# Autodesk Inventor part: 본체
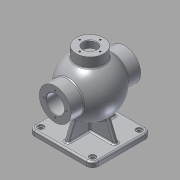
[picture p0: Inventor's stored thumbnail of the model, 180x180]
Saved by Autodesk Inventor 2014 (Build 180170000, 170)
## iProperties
Created: 2015-10
Part Number: 본체
Material: Aluminum 6061
Document SubType Name: Modeling
Designer: youjin19
Density: 2.71 g/cm^3
Appearance: Aluminum - Flat
Mass: 1524.24 g
Surface Area: 1156.04 cm^2
Volume: 562.449 cm^3
Author: youjin19
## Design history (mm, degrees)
sketch "Sketch1"
  geometry: L1 (57.5, 62.5)-(-57.5, 62.5); L2 (-57.5, 62.5)-(-57.5, -62.5); L3 (-57.5, -62.5)-(57.5, -62.5); L4 (57.5, -62.5)-(57.5, 62.5); L5 (57.5, 62.5)-(-57.5, -62.5); L6 (-57.5, 62.5)-(57.5, -62.5); 1 further point
  constraints: 12 end point, 2 midpoint, 2 parallel, 1 horizontal, 1 perpendicular
  dimensions: "d0" = 115 distance of L3.end L2.end; "d1" = 125 distance of L2.end L1.end
extrude "Extrusion1" new body sketch "Sketch1" distance "d2" = 10; taper "d3" = 0 deg
sketch "Sketch10"
  geometry: L1 (-68, 116)-(68, 116); L2 (68, 116)-(68, 85); L3 (68, 85)-(-68, 85); L4 (-68, 85)-(-68, 116); L5 (-57.5, 0)-(57.5, 0) reference; A1 r 53 centre (0, 85) between (53, 85) and (-53, 85); A2 r 53 centre (0, 85) between (-53, 85) and (53, 85); 3 further points
  constraints: 8 end point, 4 point on circle, 2 centre point, 2 midpoint, 2 parallel, 2 point on line, 1 coincident, 1 horizontal, 1 perpendicular, 1 vertical alignment
  dimensions: "d37" = 136 distance between parallel lines of L2 L4; "d38" = 62 diameter of L1 L3; "d39" = 85 distance from line of point (0, 85) L5; "d40" = 106 diameter of A1
revolve "Revolution3" sketch "Sketch10" stored, may be unused: angle "d41" = 90 deg
sketch "Sketch11"
  geometry: L1 (-57.5, -62.5)-(57.5, -62.5) reference; L2 (57.5, -62.5)-(57.5, 62.5) reference; L3 (-4, -52.5)-(4, -52.5); L4 (4, -52.5)-(4, 52.5); L5 (4, 52.5)-(-4, 52.5); L6 (-4, 52.5)-(-4, -52.5); L7 (-4, -52.5)-(4, 52.5); L8 (4, -52.5)-(-4, 52.5); L9 (-47.5, 4)-(47.5, 4); L10 (47.5, 4)-(47.5, -4); L11 (47.5, -4)-(-47.5, -4); L12 (-47.5, -4)-(-47.5, 4); L13 (-47.5, 4)-(47.5, -4); L14 (47.5, 4)-(-47.5, -4); 1 further point
  constraints: 24 end point, 4 midpoint, 4 parallel, 2 horizontal, 2 perpendicular
  dimensions: "d42" = 8 distance between parallel lines of L9 L11; "d43" = 8 distance between parallel lines of L6 L4; "d44" = 10 distance between parallel lines of L2 L10; "d45" = 10 distance between parallel lines of L1 L3
extrude "Extrusion7" join sketch "Sketch11" stored distance "d46" = 10; taper "d47" = 0 deg
feature "FaceDraft5" dims angle "d48" = 22 deg
feature "FaceDraft6" dims angle "d49" = 22 deg
feature "FaceDraft7" dims angle "d50" = 22 deg
feature "FaceDraft8" dims angle "d51" = 22 deg
sketch "Sketch12"
  geometry: L1 (-68, 54)-(-68, 116) reference; L2 (57.5, 0)-(-57.5, 0) reference; L3 (0, 85)-(-43, 85); L4 (0, 85)-(43, 85); A1 r 43 centre (0, 85) between (43, 85) and (-43, 85); A2 r 43 centre (0, 85) between (-43, 85) and (43, 85); 2 further points
  constraints: 4 end point, 4 point on circle, 2 centre point, 1 collinear, 1 horizontal alignment, 1 midpoint, 1 parallel, 1 vertical alignment
  dimensions: "d52" = 86 diameter of A1; "d53" = 85 distance from line of L3.start L2 (derived)
revolve "Revolution4" sketch "Sketch12" stored, may be unused: angle "d55" = 90 deg
sketch "Sketch13"
  geometry: C1 r 31 at (0, 0) reference; C2 r 17.5 at (0, 0); 1 further point
  constraints: 1 centre point, 1 coincident
  dimensions: "d56" = 35 diameter of C2
extrude "Extrusion8" cut sketch "Sketch13" stored distance "d57" = 10; taper "d58" = 0 deg
sketch "Sketch14"
  geometry: C1 r 31 at (0, 0) reference; C2 r 17.5 at (0, 0); 1 further point
  constraints: 1 centre point, 1 coincident
  dimensions: "d59" = 35 diameter of C2
extrude "Extrusion9" cut sketch "Sketch14" distance "d60" = 16; taper "d61" = 0 deg
sketch "Sketch15"
  geometry: C1 r 17.5 at (0, 0) reference; C2 r 18.5 at (0, 0); 1 further point
  constraints: 1 centre point, 1 coincident
  dimensions: "d62" = 37 diameter of C2
extrude "Extrusion10" cut sketch "Sketch15" distance "d63" = 1.75; taper "d64" = 0 deg
sketch "Sketch16"
  geometry: C1 r 18.5 at (0, 0) reference; C2 r 17.5 at (0, 0); 1 further point
  constraints: 1 centre point, 1 coincident
  dimensions: "d65" = 35 diameter of C2
extrude "Extrusion11" cut sketch "Sketch16" stored distance "d66" = 1.75; taper "d67" = 0 deg
fillet "Fillet1" dims "d68" = 12
sketch "Sketch17"
  geometry: L1 (45.5, 62.5)-(-45.5, 62.5) reference; L2 (-57.5, 50.5)-(-57.5, -50.5) reference; L3 (-45.5, -62.5)-(45.5, -62.5) reference; L4 (57.5, -50.5)-(57.5, 50.5) reference; L5 (4, -4)-(4, -52.5) reference; L6 (4, -52.5)-(-4, -52.5) reference; L7 (-4, -52.5)-(-4, -4) reference; L8 (-4, -4)-(-47.5, -4) reference; L9 (-47.5, -4)-(-47.5, 4) reference; L10 (-47.5, 4)-(-4, 4) reference; L11 (-4, 4)-(-4, 52.5) reference; L12 (-4, 52.5)-(4, 52.5) reference; L13 (4, 52.5)-(4, 4) reference; L14 (4, 4)-(47.5, 4) reference; L15 (47.5, 4)-(47.5, -4) reference; L16 (47.5, -4)-(4, -4) reference; A1 r 12 centre (45.5, 50.5) between (57.5, 50.5) and (45.5, 62.5) reference; A2 r 12 centre (-45.5, 50.5) between (-45.5, 62.5) and (-57.5, 50.5) reference; A3 r 12 centre (-45.5, -50.5) between (-57.5, -50.5) and (-45.5, -62.5) reference; A4 r 12 centre (45.5, -50.5) between (45.5, -62.5) and (57.5, -50.5) reference; 1 further point
hole "Hole2" diameter "d80" = 8; stored, may be unused: countersink angle "d84" = 90 deg, drill point angle "d86" = 0 deg; dims "d78" = 10, "d79" = 10, "d81" = 6, "d82" = 12, "d83" = 3, "d85" = 10
hole "Hole3" diameter "d89" = 8; stored, may be unused: countersink angle "d93" = 90 deg, drill point angle "d95" = 0 deg; dims "d87" = 10, "d88" = 10, "d90" = 6, "d91" = 12, "d92" = 3, "d94" = 10
hole "Hole4" diameter "d98" = 8; stored, may be unused: countersink angle "d102" = 90 deg, drill point angle "d104" = 0 deg; dims "d96" = 10, "d97" = 10, "d99" = 6, "d100" = 12, "d101" = 3, "d103" = 10
hole "Hole5" diameter "d107" = 8; stored, may be unused: countersink angle "d111" = 90 deg, drill point angle "d113" = 0 deg; dims "d105" = 10, "d106" = 10, "d108" = 6, "d109" = 12, "d110" = 3, "d112" = 10
workplane "Work Plane1"
sketch "Sketch18"
  geometry: C1 r 27 at (0, 0); 1 further point
  constraints: 1 centre point, 1 coincident
  dimensions: "d115" = 54 diameter of C1
extrude "Extrusion12" join sketch "Sketch18" stored distance "d116" = 1.75; taper "d117" = 0 deg
sketch "Sketch19"
  geometry: C1 r 27 at (0, 0) reference; C2 r 13 at (0, 0)
  constraints: 1 centre point, 1 coincident
  dimensions: "d118" = 26 diameter of C2
extrude "Extrusion13" cut sketch "Sketch19" stored distance "d119" = 1.75; taper "d120" = 0 deg
sketch "Sketch20"
  geometry: C1 r 17.5 at (0, 0) reference; C2 r 31 at (0, 0) reference; A1 r 22.5 centre (0, 0) between (0, 22.5) and (22.5, 0); 3 further points
  constraints: 4 point on circle, 2 horizontal alignment, 2 vertical alignment, 1 centre point, 1 coincident
  dimensions: "d121" = 45 diameter of A1
hole "Hole6" sketch "Sketch20" at (0, 22.5), (22.5, 0), (0, -22.5), (-22.5, 0) diameter "d122" = 3.242; stored, may be unused: countersink angle "d126" = 90 deg, drill point angle "d128" = 118 deg; dims "d123" = 12, "d124" = 12, "d125" = 3, "d127" = 15
sketch "Sketch21"
  geometry: C1 r 17.5 at (0, 0) reference; C2 r 31 at (0, 0) reference; A1 r 24 centre (0, 0) between (0, 24) and (24, 0); 3 further points
  constraints: 4 point on circle, 2 horizontal alignment, 2 vertical alignment, 1 centre point, 1 coincident
  dimensions: "d129" = 48 diameter of A1
hole "Hole7" sketch "Sketch21" at (0, 24), (24, 0), (0, -24), (-24, 0) diameter "d130" = 3.242; stored, may be unused: countersink angle "d134" = 90 deg, drill point angle "d136" = 118 deg; dims "d131" = 16, "d132" = 12, "d133" = 3, "d135" = 19
sketch "Sketch22"
  geometry: C1 r 13 at (0, 0) reference; C2 r 27 at (0, 0) reference; A1 r 20 centre (0, 0) between (0, 20) and (0, -20); 2 further points
  constraints: 4 point on circle, 2 horizontal alignment, 2 vertical alignment, 1 centre point, 1 coincident
  dimensions: "d137" = 40 diameter of A1
hole "Hole8" sketch "Sketch22" at (0, 20), (20, 0), (0, -20), (-20, 0) diameter "d138" = 3.242; stored, may be unused: countersink angle "d142" = 90 deg, drill point angle "d144" = 118 deg; dims "d139" = 9, "d140" = 12, "d141" = 3, "d143" = 11
workplane "Work Plane2"
sketch "Sketch23"
  geometry: L1 (-45.5, -150)-(45.5, -150) reference; L2 (-27, 0)-(-27, -19.393) reference; L3 (-27, 0)-(27, 0) reference; L4 (-27, 0)-(-27, -19.393) reference; L5 (-27, 0)-(27, 0) reference; L6 (-27, -19.393)-(27, -19.393) reference; 3 further points
  constraints: 1 midpoint, 1 vertical alignment, 1 other
  dimensions: "d145" = 27 distance from line of point (0, -10) L2 (derived); "d146" = 10 distance from line of point (0, -10) L3
emboss "Emboss1" sketch "Sketch23" dims "d147" = 0.5, "d148" = 0
fillet "Fillet2" dims "d149" = 3
fillet "Fillet3" dims "d150" = 3
fillet "Fillet4" dims "d151" = 3
fillet "Fillet5" dims "d152" = 3
fillet "Fillet6" dims "d153" = 3
fillet "Fillet7" dims "d154" = 3
chamfer "Chamfer1" distance "d155" = 1; stored, may be unused: second distance "d156" = 2, angle "d157" = 45 deg
body "Solid1"
node "Projected Loop1"
